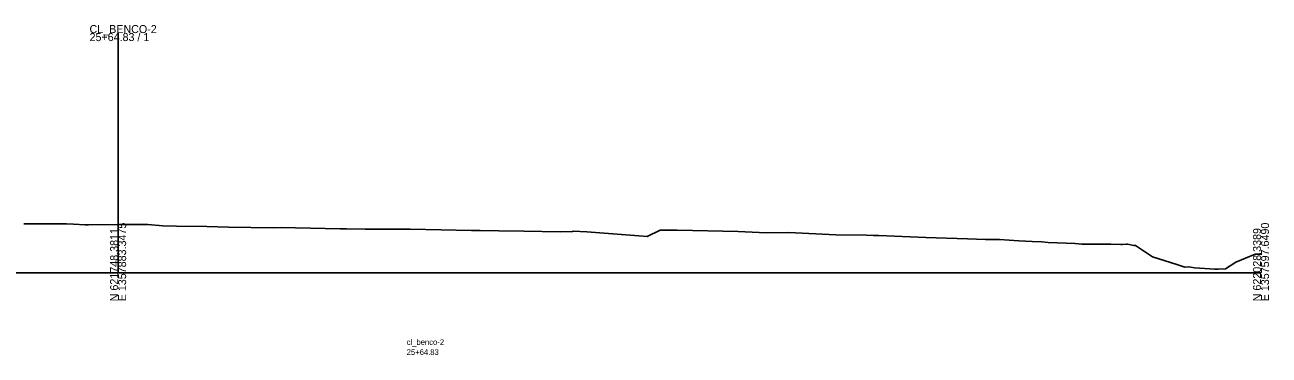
# Model space of a CAD drawing. Extents: x -26 to 803, y -28 to 2087.
# Drawn here: x 367.4 to 802.8, y 1971.2 to 2086.6 of the extents above; entities that cross this region are included whole.
import ezdxf

# ---------------------------------------------------------------- set-up
doc = ezdxf.new("R2010")
doc.units = 0
for name, color, linetype in [('DESIGN - SHEET - Light Grid', 7, 'Continuous'), ('DESIGN - TYPICAL - Warning Text', 7, 'Continuous'), ('SURVEY - GROUND - Top of Ground', 7, 'Continuous')]:
    doc.layers.add(name, color=color, linetype=linetype)

msp = doc.modelspace()

# ---------------------------------------------------------------- linework, layer by layer
at = {"layer": 'DESIGN - SHEET - Light Grid'}
for p, q in [((400, 2000), (400, 2083.71)), ((0, 2000), (400, 2000)), ((400, 2000), (800, 2000))]:
    msp.add_line(p, q, dxfattribs=at)
at = {"layer": 'SURVEY - GROUND - Top of Ground'}
msp.add_lwpolyline([(366.96, 2017.1), (381.12, 2017.06), (381.88, 2017.04), (384.36, 2016.94), (388.45, 2016.77), (389.63, 2016.72), (399.74, 2016.85), (410.07, 2016.88), (410.41, 2016.86), (415.6, 2016.36), (420.43, 2016.22), (431.01, 2016.11), (438.65, 2015.89), (454.43, 2015.63), (457.19, 2015.74), (462.08, 2015.68), (477.74, 2015.38), (479.96, 2015.34), (486.41, 2015.24), (502.27, 2015.18), (513.03, 2014.95), (523.64, 2014.77), (525.14, 2014.75), (526.73, 2014.7), (533.25, 2014.59), (541.94, 2014.47), (554.67, 2014.32), (559.03, 2014.34), (559.27, 2014.52), (564.05, 2014.22), (582.21, 2012.86), (585.21, 2012.59), (589.67, 2014.8), (592.78, 2014.84), (593.31, 2014.86), (595.62, 2014.82), (617.06, 2014.41), (626.8, 2013.92), (634.69, 2014.03), (651.17, 2013.25), (661.88, 2013.06), (664.38, 2013.02), (666.29, 2012.96), (682.67, 2012.24), (697.23, 2011.83), (703.61, 2011.57), (708.49, 2011.58), (715.27, 2011.18), (719.89, 2010.89), (723.31, 2010.75), (725.54, 2010.58), (734.92, 2010.19), (737.27, 2010), (747.43, 2009.96), (750.98, 2009.88), (751.47, 2009.84), (752.86, 2009.99), (753.22, 2010), (755.53, 2009.5), (756.08, 2009.45), (762.01, 2005.56), (770.59, 2002.86), (773.35, 2001.95), (774.47, 2002.02), (775.49, 2001.89), (776.73, 2001.7), (783.8, 2001.23), (785.01, 2001.29), (787.58, 2001.31), (791.19, 2003.64), (797.92, 2006.46), (800, 2006.53)], dxfattribs=at)

# ---------------------------------------------------------------- texts
at = {"layer": 'DESIGN - SHEET - Light Grid'}
for s, p in [('CL_BENCO-2', (390, 2083.71)), ('25+64.83 / 1', (390, 2080.91))]:
    msp.add_text(s, height=2.8, dxfattribs=at).set_placement(p)
for s, p in [('E 1357883.3475', (402.8, 1990)), ('E 1357597.6490', (802.8, 1990)), ('N 621748.3811', (400, 1990)), ('N 622028.3389', (800, 1990))]:
    msp.add_text(s, height=2.8, rotation=90, dxfattribs=at).set_placement(p)
at = {"layer": 'DESIGN - TYPICAL - Warning Text'}
for s, p in [('cl_benco-2', (501, 1974.75)), ('25+64.83', (501, 1971.25))]:
    msp.add_text(s, height=2, dxfattribs=at).set_placement(p)

doc.saveas('drawing.dxf')
